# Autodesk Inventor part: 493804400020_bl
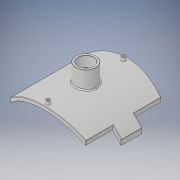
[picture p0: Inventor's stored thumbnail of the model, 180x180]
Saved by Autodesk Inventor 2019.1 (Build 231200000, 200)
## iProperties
Created: 2017-10
Part Number: 493804400020_bl
Material: Generic
Description: PLASSON BRANCH SADDLE 250-400 x 2''
Document SubType Name: Modeling
Designer: KIM
Density: 1 g/cm^3
Appearance: Default
Author: KIM
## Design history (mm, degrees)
derived "493804-2.ipt"
feature "Solid1::493804-2.ipt" dims "ScaleForDerivedMember" = 10
tag "TaggingFeature1"
body "Solid1"
other parameters: "d2" = 274.5 [user parameter], "d3" = 306 [user parameter], "d4" = 0 [user parameter], "d5" = 305 [user parameter], "d6" = 76.5 [user parameter], "d7" = 0 [user parameter], "d8" = 137.7 [user parameter], "d10" = 0 [user parameter], "d11" = 2 [user parameter], "d12" = 225.6 [user parameter], "d13" = 14 [user parameter], "d14" = 137.7 [user parameter], "d16" = 5 deg [user parameter], "d18" = 4 [user parameter], "d19" = 14 [user parameter], "d20" = 0 [user parameter], "d21" = 3 [user parameter], "d22" = 0 [user parameter], "d23" = 277 [user parameter], "d24" = 73.6528 [user parameter], "d25" = 16 [user parameter], "d26" = 56.656 [user parameter], "d28" = 0 [user parameter], "d29" = 9.6 [user parameter], "d31" = 0 [user parameter], "d32" = 53.9 [user parameter], "d33" = 0 [user parameter], "d34" = 4 [user parameter], "d35" = 0.8 [user parameter], "d36" = -38.5 [user parameter], "d38" = 53.8232 [user parameter], "d40" = 0 [user parameter], "d41" = 428 [user parameter], "d_1" = 88.7 [user parameter], "B_" = 305 [user parameter], "H_" = 77 [user parameter], "L_" = 306 [user parameter], "x_" = -26.886 [user parameter], "D_" = 16 [user parameter], "H1" = 103.886 [user parameter], "G_" = 56.656 [user parameter]
